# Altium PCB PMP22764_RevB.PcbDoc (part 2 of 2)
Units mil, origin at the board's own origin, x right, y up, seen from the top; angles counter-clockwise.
Board outline 2750 x 1770 mil, 4 copper layers (Top Layer, Signal Layer 1, Signal Layer 2, Bottom Layer), stack 61.2 mil thick; 76 components, 35 nets, 197 pads, 92 vias.
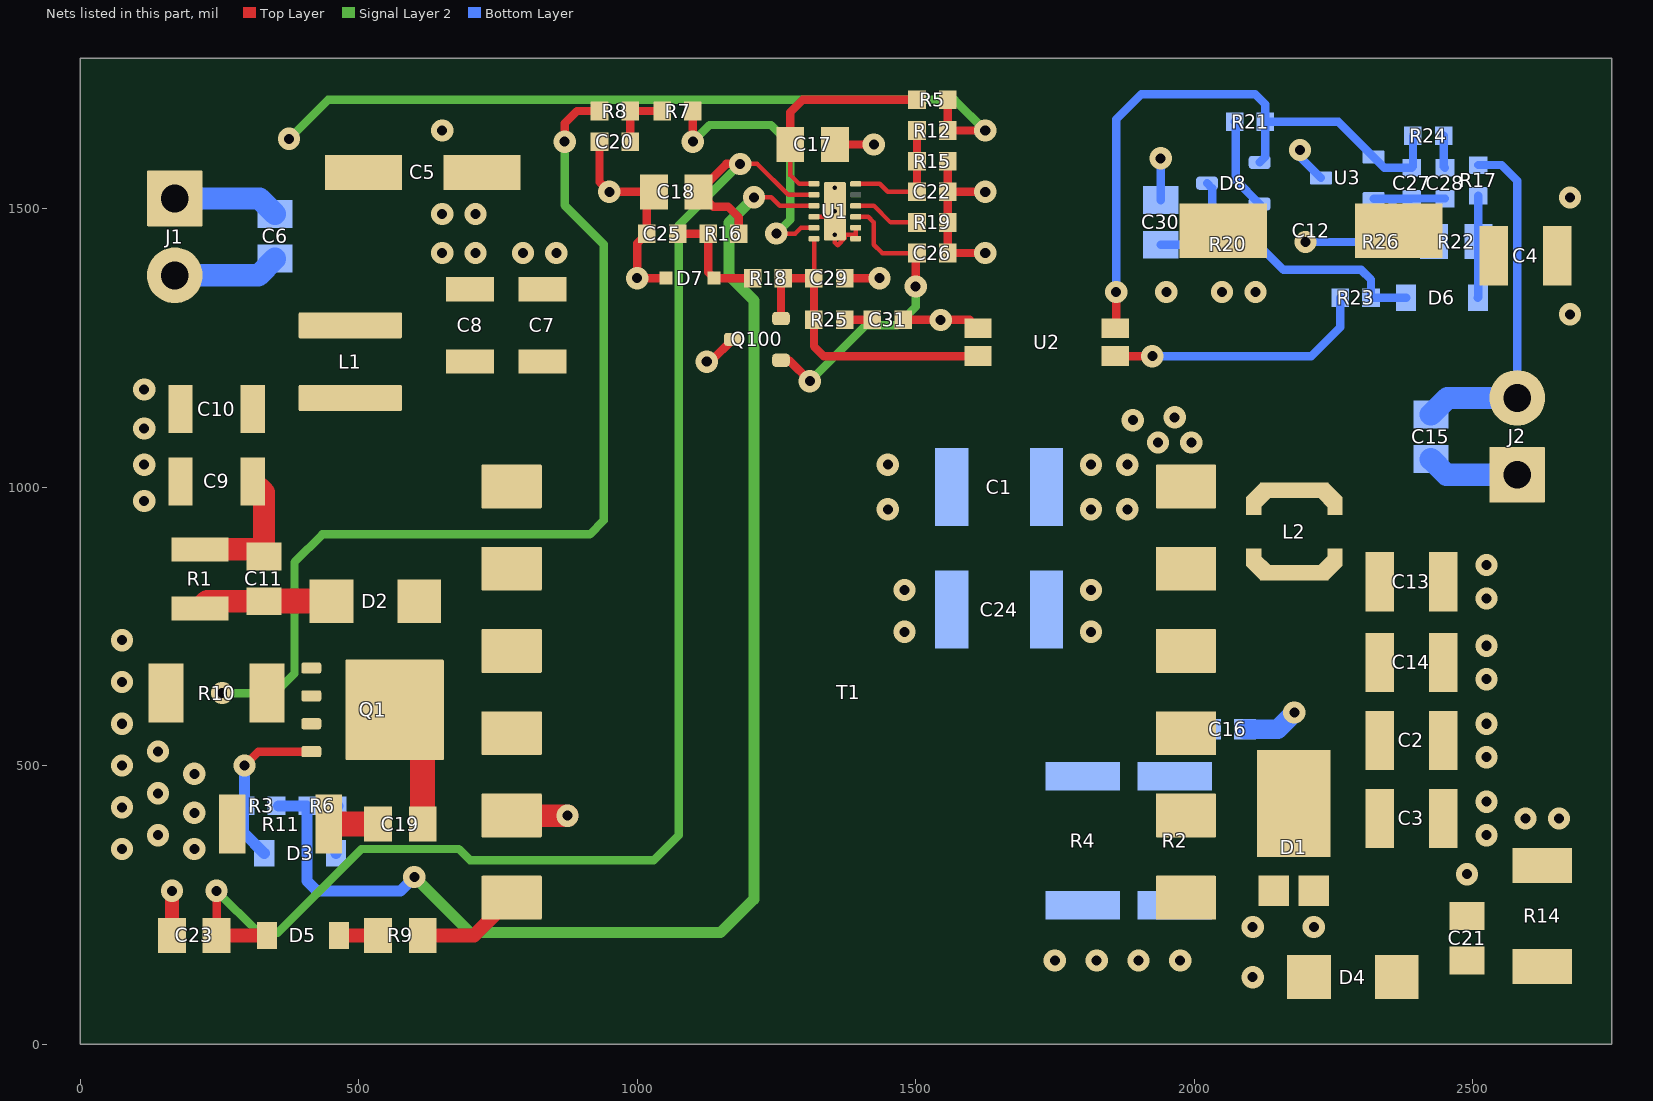
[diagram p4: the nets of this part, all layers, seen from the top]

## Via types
v1: diameter 40, hole 18, Top Layer to Bottom Layer, 89 vias
v2: diameter 19.68, hole 7.87, Top Layer to Bottom Layer, 3 vias

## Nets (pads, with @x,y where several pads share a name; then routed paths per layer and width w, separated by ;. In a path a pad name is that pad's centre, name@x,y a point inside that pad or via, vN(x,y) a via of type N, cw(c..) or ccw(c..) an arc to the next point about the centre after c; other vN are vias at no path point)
D1_K: C2.2 C3.2 C13.1 C14.1 C16.1 D1.3 L2.1 T1.8 T1.9 T1.10 T1.11 | length 100.9
  Bottom Layer w35: C16.1@2091.5,565 2150,565 v1(2180,595)
GND: C1.1 C2.1 C3.1 C4.1 C12.2 C13.2 C14.2 C15.1 C21.2 C24.1 C30.1 J2.1 R14.2 R26.2 T1.12 U3.3 | length 414.7
  Bottom Layer w15: C30.1@1940,1515 v1(1940,1590) ; v1(2190,1605) 2190,1592.76 U3.3@2227.76,1555 ; v1(2200,1440) R26.2@2307.44,1440
  Bottom Layer w40: C15.1@2425,1050 2453,1022 J2.1@2580,1022
  other v1: 2490,305 2525,375 2595,405 2655,405 2525,435 2525,515 2525,575 2525,655 2525,715 1815,740 2525,800 1815,815 2525,860 1815,960 1880,960 1815,1040 1880,1040 1935,1080 1995,1080 1890,1120 1965,1125 2675,1310 1950,1350 2050,1350 2110,1350 2675,1519.87
NetC1_2: C1.2 C7.1 C8.1 C9.1 C10.1 C11.1 L1.2 R1.1 T1.1 T1.2 | length 263.7
  Top Layer w40: R1.1@215,888.15 316.85,888.15 C11.1@330,875 330,989.96 C9.1@309.96,1010
  other v1: 1450,960 1450,1040
NetC4_2: C4.2 C12.1 C15.2 J2.2 L2.2 R17.1 | length 638.6
  Bottom Layer w15: R17.1@2510.39,1578.02 2551.98,1578.02 2580,1550 J2.2@2580,1160
  Bottom Layer w40: C15.2@2425,1130 2455,1160 J2.2@2580,1160
NetC5_1: C5.1 C6.1 J1.1 L1.1 R5.2 R12.1 | length 1615.8
  Top Layer w15: R5.2@1557.56,1695 R12.1@1557.56,1640 v1(1625,1640)
  Signal Layer 2 w15: v1(375,1625) 445,1695 1570,1695 v1(1625,1640)
  Bottom Layer w40: J1.1@170,1518 322,1518 C6.1@350,1490
NetC11_2: C11.2 D2.1 R1.2 | length 241.7
  Top Layer w40: R1.2@215,781.85 228.15,795 C11.2@330,795
  Top Layer w45: C11.2@330,795 D2.1@451.26,795
NetC16_2: C16.2 R2.2 R4.2
NetC17_2: C17.2 R5.1 U1.1 | length 398.7
  Top Layer w8: C17.2@1275,1615 1275,1560 1290.79,1544.21 U1.1@1317.6,1544.21
  Top Layer w15: C17.2@1275,1615 1275,1672.99 1297.01,1695 R5.1@1502.44,1695
NetC18_1: C18.1 C23.2 D5.1 R16.2 U1.2 | length 2743.2
  Top Layer w8: v1(1185,1580.08) 1215.55,1580.08 1271.1,1524.53 U1.2@1317.6,1524.53
  Top Layer w15: C23.2@245,195 v1(245,275) ; R16.2@1182.56,1455 1182.56,1483.9 1163.07,1503.39 1136.61,1503.39 C18.1@1110,1530 1160.08,1580.08 v1(1185,1580.08)
  Top Layer w25: C23.2@245,195 D5.1@335.53,195
  Signal Layer 2 w15: v1(245,275) 320,200 355,200 505,350 680,350 700,330 1030,330 1075,375 1075,1470.08 v1(1185,1580.08)
NetC19_1: C19.1 D2.2 Q1.5 Q1.6 Q1.7 Q1.8 Q1.9@564.61,600 T1.3 T1.4 | length 229.3
  Top Layer w45: Q1.9@564.61,600 565,600.39 610.47,554.92 615,554.92 C19.1@615,395
NetC19_2: C19.2 R11.2 | length 88.4
  Top Layer w45: R11.2@446.61,395 C19.2@535,395
NetC20_2: C20.2 R7.2 R8.1 | length 112.4
  Top Layer w15: C20.2@987.56,1620 R8.1@987.56,1675 R7.2@1045,1675
NetC21_1: C21.1 D4.2 R14.1
NetC22_2: C22.2 R12.2 R15.1 U1.12 | length 225.9
  Top Layer w8: U1.12@1392.4,1544.21 1435.79,1544.21 1450,1530 C22.2@1502.44,1530
  Top Layer w15: C22.2@1502.44,1530 R15.1@1502.44,1585 R12.2@1502.44,1640
NetC25_1: C25.1 D7.1 R16.1 R18.1 | length 208.5
  Top Layer w15: C25.1@1072.56,1455 R16.1@1127.44,1455 1127.44,1385.87 D7.1@1138.31,1375 R18.1@1207.44,1375
NetC26_1: C26.1 Q100.1 U1.9 | length 570.6
  Top Layer w8: U1.9@1392.4,1485.16 1414.84,1485.16 1425,1475 1425,1435 1440,1420 1497.44,1420 C26.1@1502.44,1420
  Top Layer w15: Q100.1@1258.31,1227.6 1272.4,1227.6 v1(1310,1190) ; v1(1500,1360) 1500,1417.56 C26.1@1502.44,1420
  Signal Layer 2 w15: v1(1310,1190) 1410.16,1290.16 1466.73,1290.16 1500,1323.43 v1(1500,1360)
NetC27_1: C27.1 C28.1 R22.2 R26.1 U3.2 | length 276.5
  Bottom Layer w15: U3.2@2322.24,1517.6 2356.17,1517.6 ; R22.2@2430.39,1440.46 2429.94,1440 R26.1@2362.56,1440 2362.56,1484.86 2356.17,1491.25 2356.17,1517.6 ; C28.1@2450.39,1517.9 C27.1@2390.39,1517.9 2390.09,1517.6 2356.17,1517.6
NetC27_2: C27.2 D8.1 R21.2 R24.1 U2.2 U3.1 | length 1133.3
  Top Layer w15: U2.2@1858.03,1285 1860,1286.97 v1(1860,1350)
  Bottom Layer w15: v1(1860,1350) 1860,1660 1905,1705 2110,1705 2127.95,1687.05 R21.2@2127.95,1655.46 ; D8.1@2117.64,1582.86 2127.95,1593.17 R21.2@2127.95,1655.46 ; R24.1@2392.83,1630.46 2392.83,1575.46 C27.2@2390.39,1573.02 2341.63,1573.02 U3.1@2322.24,1592.4 2259.19,1655.46 R21.2@2127.95,1655.46
NetC28_2: C28.2 R24.2 | length 58.5
  Bottom Layer w15: R24.2@2447.95,1630.46 2447.95,1575.46 C28.2@2450.39,1573.02
NetC29_2: C29.2 Q100.2 R18.2 R25.2 U1.6 U2.4 | length 624.3
  Top Layer w8: C29.2@1317.44,1375 1317.6,1375.16 U1.6@1317.6,1445.79
  Top Layer w15: Q100.2@1258.31,1302.4 1258.31,1370.75 R18.2@1262.56,1375 C29.2@1317.44,1375 R25.2@1317.44,1300 1317.44,1252.56 1335,1235 U2.4@1611.97,1235
NetC30_2: C30.2 D8.3 R20.2 | length 206.7
  Bottom Layer w15: C30.2@1940,1435 2032.38,1435 2032.38,1536.23 D8.3@2023.15,1545.46
NetC31_1: C31.1 R25.1 | length 49.9
  Top Layer w15: R25.1@1372.56,1300 C31.1@1422.44,1300
NetD1_1: D1.1 D1.2 D4.1 R2.1 R4.1 T1.7
  other v1: 2105,120 1750,150 1825,150 1900,150 1975,150 2105,210 2215,210
NetD3_1: D3.1 R6.2 | length 86.3
  Bottom Layer w20: D3.1@459.47,342.5 459.47,424.41 R6.2@462.56,427.5
NetD3_2: D3.2 Q1.4 R3.2 | length 303.8
  Top Layer w15: v1(295,500) 320,525 Q1.4@415,525
  Bottom Layer w20: v1(295,500) 295,429 293.5,427.5 293.5,379.53 D3.2@330.53,342.5
NetD5_2: D5.2 R9.2 | length 70.5
  Top Layer w25: D5.2@464.47,195 R9.2@535,195
NetD6_1: D6.1 R17.2 R22.1 | length 183.3
  Bottom Layer w15: D6.1@2509.47,1340 2510.39,1340.93 R22.1@2510.39,1440.46 R17.2@2510.39,1522.9
NetD6_2: D6.2 D8.2 R20.1 R21.1 R23.1 | length 590.8
  Bottom Layer w15: R21.1@2072.83,1655.46 2075,1653.29 2075,1550.69 D8.2@2117.64,1508.06 2117.64,1438.09 2115,1435.46 ; R20.1@2087.95,1435.46 2115,1435.46 ; D6.2@2380.53,1340 R23.1@2317.56,1340 2317.56,1372.44 2300,1390 2160.46,1390 2115,1435.46
NetQ1_1: Q1.1 Q1.2 Q1.3 R8.2 R10.2 | length 1744.1
  Top Layer w15: v1(870,1620) 870,1652.99 892.01,1675 R8.2@932.44,1675
  Signal Layer 2 w15: v1(255,630) 350,630 385,665 385,865 435,915 915,915 940,940 940,1435.83 870,1505.83 v1(870,1620)
NetR3_1: R3.1 R6.1 U1.3 | length 2483.6
  Top Layer w8: v1(1210,1520.08) 1240.92,1520.08 1256.16,1504.84 U1.3@1317.6,1504.84
  Signal Layer 2 w20: v1(600,300) 700,200 1150,200 1210,260 1210,1335 1165,1380 1165,1475.08 v1(1210,1520.08)
  Bottom Layer w20: R3.1@356.5,427.5 R6.1@407.44,427.5 407.44,292.56 425,275 575,275 v1(600,300)
NetR7_1: R7.1 U1.5 | length 499.3
  Top Layer w8: v1(1250,1455.08) 1283.78,1455.08 1294.17,1465.47 U1.5@1317.6,1465.47
  Top Layer w15: v1(1100,1620) 1100,1674.88 R7.1@1100.12,1675
  Signal Layer 2 w15: v1(1100,1620) 1130,1650 1240.31,1650 1275,1615.31 1275,1480.08 v1(1250,1455.08)
NetR9_1: R9.1 T1.6 | length 187.6
  Top Layer w25: R9.1@615,195 707.24,195 T1.6@774.69,262.44
NetR19_1: R19.1 U1.10 | length 122.4
  Top Layer w8: U1.10@1392.4,1504.84 1425.16,1504.84 1455,1475 R19.1@1502.44,1475
NetR23_2: R23.2 U2.1 | length 479
  Top Layer w15: U2.1@1858.03,1235 v1(1925,1235)
  Bottom Layer w15: v1(1925,1235) 2210.47,1235 2262.44,1286.97 R23.2@2262.44,1340
PGND: C5.2 C6.2 C7.2 C8.2 C9.2 C10.2 C17.1 C18.2 C20.1 C22.1 C23.1 C24.2 C25.2 C26.2 C29.1 C31.2 D7.2 J1.2 Q100.3 R10.1 R11.1 R15.2 R19.2 T1.5 U1.4 U1.7 U1.8 U1.13 U2.3 | length 1574.6
  Top Layer w8: U1.4@1317.6,1485.16 1345.16,1485.16 v2(1355,1495) 1355,1438.98 1360,1433.98 1372.99,1446.97 1372.99,1452.85 1389.62,1452.85 1392.4,1455.63 ; U1.7@1392.4,1445.79 1392.4,1455.63 ; U1.8@1392.4,1465.47 1392.4,1455.63
  Top Layer w15: C20.1@932.44,1620 932.44,1547.56 v1(950,1530) C18.2@1030,1530 1017.44,1517.44 C25.2@1017.44,1455 1000,1437.56 v1(1000,1375) D7.2@1051.69,1375 ; v1(1125,1225) 1131.69,1225 Q100.3@1171.69,1265 ; C17.1@1355,1615 v1(1425,1615) ; C29.1@1372.56,1375 v1(1435,1375) ; C31.2@1477.56,1300 v1(1545,1300) 1596.97,1300 U2.3@1611.97,1285 ; R15.2@1557.56,1585 C22.1@1557.56,1530 ; v1(1625,1420) C26.2@1557.56,1420 R19.2@1557.56,1475 C22.1@1557.56,1530 ; v1(1625,1530) C22.1@1557.56,1530
  Top Layer w25: C23.1@165,195 v1(165,275)
  Top Layer w40: T1.5@774.68,410.39 775.08,410 v1(875,410)
  Bottom Layer w40: J1.2@170,1380 320,1380 C6.2@350,1410
  other v1: 75,350 205,350 140,375 205,415 75,425 140,450 205,485 75,500 140,525 75,575 75,650 75,725 1480,740 1480,815 115,975 115,1040 115,1105 115,1175 650,1420 710,1420 795,1420 855,1420 650,1490 710,1490 650,1640
  other v2: 1355,1452.68 1355,1537.32
pads on no net: Q1.9@510.08,542.91 Q1.9@510.08,600 Q1.9@510.08,657.09 Q1.9@546.69,600 Q1.9@580.16,542.91 Q1.9@580.16,600 Q1.9@580.16,657.09 U1.11

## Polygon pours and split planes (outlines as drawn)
PGND on Bottom Layer "BOTTOM_LAYER_PGND_P076" (solid, remove dead copper, pour order 76): 50,50 50,1720 1680,1720 1680,1200 1595,1200 1595,50
GND on Bottom Layer "BOTTOM_LAYER_GND_P066" (solid, remove dead copper, pour order 66): 2700,50 1705,50 1705,1090 1790,1090 1790,1720 2700,1720
NetC16_2 on Bottom Layer "BOTTOM_LAYER_NETC16_2_P062" (solid, remove dead copper, pour order 62): 1725,335 2050,335 2050,600 1725,600
NetD1_1 on Bottom Layer "BOTTOM_LAYER_NETD1_1_P060" (solid, remove dead copper, pour order 60): 2260,305 2260,50 1705,50 1705,305
NetC1_2 on Bottom Layer "BOTTOM_LAYER_NETC1_2_P058" (solid, remove dead copper, pour order 58): 1595,1070 1400,1070 1400,930 1595,930
no net on Bottom Layer "BOTTOM_LAYER_NONET_P000" (solid, remove dead copper, pour order 0): 90,760
no net on Bottom Layer "BOTTOM_LAYER_NONET_P002" (solid, remove dead copper, pour order 2): 106.57,762.09
PGND on Top Layer "TOP_LAYER_PGND_P074" (solid, remove dead copper, pour order 74): 1680,1720 1680,1200 1595,1200 1595,50 50,50 50,1720
GND on Top Layer "TOP_LAYER_GND_P068" (solid, remove dead copper, pour order 68): 2700,50 1705,50 1705,1090 1790,1090 1790,1720 2700,1720
NetC21_1 on Top Layer "TOP_LAYER_NETC21_1_P056" (solid, remove dead copper, pour order 56): 2700,50 2300,50 2300,175 2700,175
NetC4_2 on Top Layer "TOP_LAYER_NETC4_2_P054" (solid, remove dead copper, pour order 54): 2085,945 2085,1250 2250,1250 2250,1700 2580,1700 2580,1250 2700,1250 2700,1105 2450,1105 2450,945
D1_K on Top Layer "TOP_LAYER_D1_K_P052" (solid, remove dead copper, pour order 52): 2375,335 1705,335 1705,600 1900,600 1900,895 2375,895
NetD1_1 on Top Layer "TOP_LAYER_NETD1_1_P050" (solid, remove dead copper, pour order 50): 2260,305 1705,305 1705,50 2260,50
NetQ1_1 on Top Layer "TOP_LAYER_NETQ1_1_P048" (solid, remove dead copper, pour order 48): 435,700 435,565 235,565 235,700
NetC19_1 on Top Layer "TOP_LAYER_NETC19_1_P046" (solid, remove dead copper, pour order 46): 830,765 680,765 680,865 550,865 550,700 475,700 475,500 830,500
NetC1_2 on Top Layer "TOP_LAYER_NETC1_2_P044" (solid, remove dead copper, pour order 44): 900,930 1500,930 1500,1070 900,1070 900,1270 635,1270 635,1185 270,1185 270,950 715,950 715,800 900,800
NetC5_1 on Top Layer "TOP_LAYER_NETC5_1_P043" (solid, remove dead copper, pour order 43): 50,1465 300,1465 300,1265 600,1265 600,1720 50,1720
GND on Signal Layer 1 "SIGNAL_LAYER_1_GND_P064" (solid, remove dead copper, pour order 64): 1705,50 2700,50 2700,1720 1790,1720 1790,1090 1705,1090
PGND on Signal Layer 1 "SIGNAL_LAYER_1_PGND_P072" (solid, remove dead copper, pour order 72): 1595,50 50,50 50,1720 1680,1720 1680,1200 1595,1200
GND on Signal Layer 2 "SIGNAL_LAYER_2_GND_P070" (solid, remove dead copper, pour order 70): 1705,50 1705,1090 1790,1090 1790,1720 2700,1720 2700,50
PGND on Signal Layer 2 "SIGNAL_LAYER_2_PGND_P078" (solid, remove dead copper, pour order 78): 50,1720 50,50 1595,50 1595,1200 1680,1200 1680,1720

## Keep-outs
Keep-Out Layer:
  text ".Layer_Name" at 577,-858.49 h60

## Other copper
Top Layer:
  text ".Layer_Name" at 577,-858.49 h60
Bottom Layer:
  text ".Layer_Name" at 577,-858.49 h60

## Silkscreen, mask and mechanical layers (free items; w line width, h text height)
Top Overlay:
  text "VIN" at 130,1610 h50
  text "VOUT" at 2500,1267.09 h50
  text "RTN" at 120,1240 h50
  text "GND" at 2595,888.15 h50
  text ".Layer_Name" at 577,-858.49 h60
Bottom Overlay:
  text "'.PRJ_Number'.PCB_Rev" at 1339.25,750 h108.27
  text ".Layer_Name" at 577,-858.49 h60
Top Paste:
  text ".Layer_Name" at 577,-858.49 h60
Bottom Paste:
  text ".Layer_Name" at 577,-858.49 h60
Top Solder:
  text ".Layer_Name" at 577,-858.49 h60
  text ".Layer_Name" at 577,-858.49 h60
Bottom Solder:
  text ".Layer_Name" at 577,-858.49 h60
Drill Guide:
  text ".Layer_Name" at 577,-858.49 h60
M1 Board Outline:
  the board outline again, w10
  text ".Layer_Name" at 577,-858.49 h60
M2 Board Dimensions:
  rectangle: 0,-275 125,-150
  rectangle: 125,-400 500,-275
  lines w7: 0,-275 1000,-275 ; 125,-400 125,-150 ; 250,-400 250,-150 ; 500,-400 500,-150 ; 750,-400 750,-150 ; 0,-400 1000,-400 1000,-150 0,-150 0,-400
  text ".Layer_Name" at 577,-858.49 h60
M3 3D STEP Top:
  text ".Layer_Name" at 577,-858.49 h60
M4 3D STEP Bottom:
  text ".Layer_Name" at 577,-858.49 h60
M5 Assembly Top:
  lines w10: -292,-930.17 6308,-930.17 ; -292,-726.83 6310,-726.83 ; -292,-523.5 -292,-1133.5 3713,-1133.5 6310,-1133.5 6310,-523.5 -291.5,-523.5 -291.5,-1133.5 1284,-1133.5 ; 2173,-1133.5 2173,-523.5 ; 3440,-726.83 3440,-523.5 ; 4280,-726.83 4280,-523.5 ; 4902,-1140 4902,-937.17
  text "COMPONENTS MARKED 'DNP' SHOULD NOT BE POPULATED." at 1153.5,-318.5 h60
  text "ASSEMBLY VARIANT:" at 1153,-434 h60
  text ".VariantName" at 2189,-434 h60
  text "PCB VIEWED FROM TOP SIDE" at -228.5,-655.67 h60
  text "BOARD #:" at 2248,-655.67 h60
  text ".PRJ_Number" at 2793.5,-655.67 h60
  text "REV:" at 3638,-655.67 h60
  text ".PCB_Rev" at 3929.5,-655.67 h60
  text "SVN REV:" at 4476,-655.67 h60
  text ".VersionControl_RevNumber" at 4982,-655.67 h60
  text "TID #:" at 2248,-859 h60
  text ".TID" at 2793.5,-859 h60
  text "PLOT NAME =" at -228.5,-1064.34 h60
  text ".plot_File_Name" at 577,-1064.34 h60
  text "GENERATED    :" at 2250,-1064.34 h60
  text ".Print_Date" at 3119.5,-1064.34 h60
  text ".Print_Time" at 3848.5,-1064.34 h60
  text "TEXAS INSTRUMENTS" at 5113,-1064.34 h60
M6 Assembly Bottom:
  lines w10: -292.5,-727.33 6309.5,-727.33 ; -290.5,-930.67 6309.5,-930.67 ; 1115.5,-1140.5 1115.5,-937.67 ; 1737.5,-727.33 1737.5,-524 ; 2577.5,-727.33 2577.5,-524 ; 3844.5,-1134 3844.5,-524 ; 4733.5,-1134 6309,-1134 6309,-524 -292.5,-524 -292.5,-1134 2304.5,-1134 6309.5,-1134 6309.5,-524
  text "COMPONENTS MARKED 'DNP' SHOULD NOT BE POPULATED." at 6102,-318 h60
  text ".VariantName" at 5058,-434 h60
  text "ASSEMBLY VARIANT:" at 6097,-434 h60
  text ".VersionControl_RevNumber" at 1035.5,-656.17 h60
  text "SVN REV:" at 1541.5,-656.17 h60
  text ".PCB_Rev" at 2088,-656.17 h60
  text "REV:" at 2379.5,-656.17 h60
  text ".PRJ_Number" at 3224,-656.17 h60
  text "BOARD #:" at 3769.5,-656.17 h60
  text "PCB VIEWED FROM BOTTOM SIDE" at 6246,-656.17 h60
  text ".TID" at 3224,-859.5 h60
  text "TID #:" at 3769.5,-859.5 h60
  text "TEXAS INSTRUMENTS" at 904.5,-1064.84 h60
  text ".Print_Time" at 2169,-1064.84 h60
  text ".Print_Date" at 2898,-1064.84 h60
  text "GENERATED    :" at 3767.5,-1064.84 h60
  text ".plot_File_Name" at 5440.5,-1064.84 h60
  text "PLOT NAME =" at 6246,-1064.84 h60
M9 Title Sheet:
  drawing of 57 lines, arcs and shapes, not listed
  text "1" at 739.84,8036.5 h70
  text "2" at 3235.5,8036.5 h70
  text "3" at 5724.84,8036.5 h70
  text "4" at 8231.51,8036.5 h70
  text "5" at 10730.5,8036.5 h70
  text "6" at 13235.5,8036.5 h70
  text "A" at -416.5,6893.5 h70
  text "A" at 14383.5,6893.5 h70
  text "B" at -416.5,4513.5 h70
  text "B" at 14383.5,4513.5 h70
  text "C" at -416.5,2138.5 h70
  text "C" at 14383.5,2138.5 h70
  text "PROJECT TITLE:" at 11343.5,277.5 h45
  text ".PRJ_Title" at 11393.5,144.17 h70
  text "DESIGNED FOR:" at 11343.5,-23.5 h45
  text ".PRJ_Customer" at 11393.5,-163.5 h70
  text "D" at -416.5,-231.5 h70
  text "D" at 14383.5,-231.5 h70
  text "FILE NAME:" at 11343.5,-323.5 h45
  text ".PCB_File_Name_No_Path" at 11393.5,-443.5 h70
  text "Texas Instruments (TI) and/or its licensors do not warrant the accuracy or completeness of this specification" at 6374,-605.34 h45
  text "ENGINEER:" at 11343.5,-613.5 h45
  text "LAYOUT BY:" at 12848.5,-613.5 h45
  text "or any information contained therein. TI and/or its licensors do not warrant that this design will meet" at 6329.01,-718 h45
  text ".PRJ_Engineer" at 11393.5,-768.49 h70
  text ".PCB_Layout" at 12899,-768.49 h70
  text "the specifications, will be suitable for your application or fit for any particular purpose, or will operate in" at 6329.01,-830.67 h45
  text ".Layer_Name" at 577,-858.49 h60
  text "ALTIUM DESIGNER VERSION:" at 12848.5,-923.5 h45
  text "an implementation. TI and/or its licensors do not warrant that the design is production worthy. You should" at 6329.01,-943.33 h45
  text "completely validate and test your design implementation to confirm the system functionality for your application." at 6374,-1056 h45
  text ".print_Scale" at 11393.5,-1056.83 h70
  text ".Application_BuildNumber" at 12899,-1056.83 h70
  text "1" at 739.84,-1263.5 h70
  text "2" at 3235.5,-1263.5 h70
  text "3" at 5724.84,-1263.5 h70
  text "4" at 8231.51,-1263.5 h70
  text "5" at 10730.5,-1263.5 h70
  text "6" at 13235.5,-1263.5 h70
M10 Fab Notes:
  drawing of 189 lines, arcs and shapes, not listed
  text "DESIGN INFORMATION" at 12382.02,6356.17 h60
  text "MIN. TRACK WIDTH:" at 11737.46,6224.05 h60
  text "8" at 12833.7,6224.05 h60
  text "MIL" at 12988.46,6224.05 h60
  text "MIN. CLEARANCE:" at 11737.46,6099.92 h60
  text "0.2" at 12773.7,6099.93 h60
  text "mm" at 12988.46,6099.92 h60
  text "MIN. VIA PAD SIZE:" at 11737.46,5975.8 h60
  text "24" at 12803.71,5975.8 h60
  text "MIL" at 12988.46,5975.8 h60
  text "0.05mm (2MIL)" at 12432.46,5845.9 h60
  text "MINIMUM ANNULAR RING" at 11408.23,5837.67 h60
  text "EXTERNAL" at 13140.46,5837.67 h60
  text "PER" at 11608.23,5727.55 h60
  text "IPC-D-275 CLASS 2 LEVEL C" at 11828.23,5727.54 h60
  text "MIL, HOLES" at 13316.46,5627.07 h60
  text "+/-" at 12924,5618.48 h60
  text "+/-" at 13778,5618.48 h60
  text "REGISTRATION TOLERANCES:" at 11408.23,5617.42 h60
  text "METAL" at 12608,5617.42 h60
  text "5" at 13184.2,5617.42 h60
  text "3" at 14017.2,5617.42 h60
  text "MIL" at 14133.46,5617.42 h60
  text "HOLE SIZE TOLERANCE (UNLESS OTHERWISE SPECIFIED):" at 11408.23,5519.1 h60
  text "+/-" at 13778,5516.23 h60
  text "3" at 14017.2,5515.17 h60
  text "MIL" at 14133.46,5515.17 h60
  text "MATERIAL:" at 11333.46,5377.52 h60
  text "FR-4 High Tg" at 12319.9,5249 h60
  text "X" at 12175.46,5241.01 h60
  text "FR-408" at 11754.46,5236.49 h60
  text "OTHER" at 13242.46,5236.49 h60
  text "62 MIL (1.6mm) +/-10%" at 12074.56,5093.46 h60
  text "X" at 11954.46,5091.01 h60
  text "THICKNESS:" at 11408.23,5085.24 h60
  text "OTHER" at 13359.46,5085.24 h60
  text "TOLERANCE:" at 11408.23,4946.92 h60
  text "X" at 12256.46,4946.92 h60
  text "ANSI IPC-6012 TYPE 3 CLASS 2" at 12434.48,4946.92 h60
  text "OTHER +/-" at 12434.46,4802.73 h60
  text "BOW & TWIST:" at 11408.23,4657.54 h60
  text "X" at 12256.46,4657.54 h60
  text "ANSI IPC-6012 TYPE 3 CLASS 2" at 12434.48,4657.54 h60
  text "OTHER +/-" at 12434.46,4510.85 h60
  text "DRILLING:" at 11333.46,4380.23 h60
  text "NC_DRILL FILES" at 13094.46,4275.04 h60
  text "REFERENCE:" at 11408.23,4271.1 h60
  text "X" at 12065.46,4271.01 h60
  text "AS SHOWN" at 12243.46,4271.1 h60
  text "X" at 12966.46,4271.1 h60
  text "OTHER" at 13392.46,4128.85 h60
  text "PTH COPPER THICKNESS:" at 11407.91,4125.32 h60
  text "X" at 12547.14,4125.32 h60
  text "20-30 um" at 12675.14,4125.32 h60
  text "BOARD FINISH:" at 11333.46,3977.73 h60
  text "SILKSCREEN:" at 11488.68,3867.6 h60
  text "X" at 12446.46,3867.6 h60
  text "TOP" at 12563.46,3867.6 h60
  text "X" at 12956.46,3867.6 h60
  text "BOTTOM" at 13074.46,3867.6 h60
  text "SILKSCREEN COLOR:" at 11488.68,3712.41 h60
  text "X" at 12445.46,3712.41 h60
  text "WHITE" at 12563.46,3712.41 h60
  text "OTHER" at 13074.46,3712.41 h60
  text "X" at 12576.46,3568.96 h60
  text "GREEN" at 12694.46,3568.96 h60
  text "OTHER" at 13312.46,3568.96 h60
  text "SOLDER RESIST COLOR:" at 11488.68,3562.1 h60
  text "X" at 12576.46,3414.71 h60
  text "MATTE" at 12694.46,3414.71 h60
  text "SEMI-GLOSS" at 13312,3414.07 h60
  text "IMMERSION GOLD (ENIG)" at 12394.46,3241.94 h60
  text "ENEPIG" at 13732,3234.72 h60
  text "SURFACE FINISH:" at 11333.46,3233.72 h60
  text "X" at 12216.46,3233.72 h60
  text "IMM. TIN/SILVER OR EQUIV" at 11663,3096.4 h60
  text "OTHER" at 13094.46,3092.47 h60
  text "ARRAY/PANEL:" at 11333.46,2937.09 h60
  text "X" at 12210,2935 h60
  text "CUT AND TRIM PER M1 BOARD OUTLINE" at 12394.46,2928.87 h60
  text "N.C. ROUTE" at 12394.46,2792.9 h60
  text "V. SCORE" at 13260.46,2792.9 h60
  text "CERTIFICATION:" at 11333.46,2663.77 h60
  text "MATERIALS AND WORKMANSHIP FOR ALL PCBS" at 12058.46,2663.77 h60
  text "TO MEET OR EXCEED THE REQUIREMENTS OF:" at 12058.46,2569.71 h60
  text "X" at 11695.97,2441.08 h60
  text "ANSI IPC-A-600F CLASS ->" at 11823.96,2441.08 h60
  text "X" at 13471.97,2441.08 h60
  text "2" at 13581.96,2441.08 h60
  text "1" at 13266.96,2439.58 h60
  text "3" at 13935.96,2439.58 h60
  text "X" at 12507.97,2293.39 h60
  text "RoHS" at 12635.96,2293.39 h60
  text "OTHER" at 13280.36,2293.39 h60
  text "PER ORDER" at 13677.42,2293.39 h60
  text "ALL BOARDS MUST MEET OR EXCEED UL94-V0 REQUIREMENTS." at 11361,2139.57 h60
  text "PCB MUST BEAR THE UL94V-0 UL REGISTERED MATERIAL ID NUMBER" at 11361,2023.5 h60
  text "ADDITIONAL REQUIREMENTS:" at 11333.46,1854.08 h60
  text "MICROSECTION:" at 11408.23,1746.95 h60
  text "YES" at 12313.96,1746.95 h60
  text "REQUIRED" at 13175.46,1602.62 h60
  text "BARE BOARD ELEC. TEST:" at 11408.23,1599.76 h60
  text "NONE" at 12713.96,1599.76 h60
  text "X" at 13057.46,1599.76 h60
  text "PER ORDER" at 13767.46,1599.76 h60
  text "XX MIL VIAS REQUIRE NON-CONDUCTIVE FILL AND PLANARIZE" at 11576.38,1394.82 h59
  text "XX MIL VIAS REQUIRE CONDUCTIVE FILL AND PLANARIZE" at 11584.38,1290.84 h60
  text "OUTER XX MIL TRACES REQUIRE 50 OHM SINGLE-ENDED IMPEDANCE" at 11583.39,1127.46 h58
  text "LAYER 2 & 3 (INNER LAYERS) XX MIL WIDE, XX MIL SPACE / TRACES REQUIRE 100 OHM DIFFERENTIAL IMPEDANCE" at 11575.39,891.74 h60
  text ".Layer_Name" at 577,-858.49 h60
M11 Gerber Information:
  lines w10: -292,-930.17 6308,-930.17 ; -292,-726.83 6310,-726.83 ; -292,-523.5 -292,-1133.5 3713,-1133.5 6310,-1133.5 6310,-523.5 -291.5,-523.5 -291.5,-1133.5 1284,-1133.5 ; 2173,-1133.5 2173,-523.5 ; 3440,-726.83 3440,-523.5 ; 4280,-726.83 4280,-523.5 ; 4902,-1140 4902,-937.17
  text "ALL ARTWORK VIEWED FROM TOP SIDE" at -228.5,-655.67 h60
  text "BOARD #:" at 2248,-655.67 h60
  text ".PRJ_Number" at 2793.5,-655.67 h60
  text "REV:" at 3638,-655.67 h60
  text ".PCB_Rev" at 3929.5,-655.67 h60
  text "SVN REV:" at 4476,-655.67 h60
  text ".VersionControl_RevNumber" at 4982,-655.67 h60
  text "LAYER NAME =" at -228.5,-858.49 h60
  text "TID #:" at 2248,-859 h60
  text ".TID" at 2793.5,-859 h60
  text "PLOT NAME =" at -228.5,-1064.34 h60
  text ".plot_File_Name" at 577,-1064.34 h60
  text "GENERATED    :" at 2250,-1064.34 h60
  text ".Print_Date" at 3119.5,-1064.34 h60
  text ".Print_Time" at 3848.5,-1064.34 h60
  text "TEXAS INSTRUMENTS" at 5113,-1064.34 h60
M12 Stackup:
  drawing of 295 lines, arcs and shapes, not listed
  text "Layer" at 9770.88,7839.68 h60
  text "Name" at 10180.8,7839.68 h60
  text "Material" at 11120.54,7839.68 h60
  text "Thickness" at 11980.3,7839.68 h60
  text "Constant" at 12630.14,7839.68 h60
  text "Board Layer Stack" at 13200,7839.68 h60
  text "1" at 9770.88,7719.68 h60
  text "Top Overlay" at 10180.8,7719.68 h60
  text "2" at 9770.88,7599.68 h60
  text "Top Solder" at 10180.8,7599.68 h60
  text "Solder Resist" at 11120.54,7599.68 h60
  text "0.40mil" at 11980.3,7599.68 h60
  text "3.5" at 12630.14,7599.68 h60
  text "3" at 9770.88,7479.68 h60
  text "Top Layer" at 10180.8,7479.68 h60
  text "Copper" at 11120.54,7479.68 h60
  text "2.80mil" at 11980.3,7479.68 h60
  text "4" at 9770.88,7359.68 h60
  text "Dielectric1" at 10180.8,7359.68 h60
  text "FR-4" at 11120.54,7359.68 h60
  text "15.00mil" at 11980.3,7359.68 h60
  text "4.8" at 12630.14,7359.68 h60
  text "5" at 9770.88,7239.68 h60
  text "Signal Layer 1" at 10180.8,7239.68 h60
  text "Copper" at 11120.54,7239.68 h60
  text "2.80mil" at 11980.3,7239.68 h60
  text "6" at 9770.88,7119.68 h60
  text "Dielectric 2" at 10180.8,7119.68 h60
  text "20.00mil" at 11980.3,7119.68 h60
  text "4.2" at 12630.14,7119.68 h60
  text "7" at 9770.88,6999.68 h60
  text "Signal Layer 2" at 10180.8,6999.68 h60
  text "Copper" at 11120.54,6999.68 h60
  text "2.80mil" at 11980.3,6999.68 h60
  text "8" at 9770.88,6879.68 h60
  text "Dielectric 3" at 10180.8,6879.68 h60
  text "FR-4" at 11120.54,6879.68 h60
  text "15.00mil" at 11980.3,6879.68 h60
  text "4.2" at 12630.14,6879.68 h60
  text "9" at 9770.88,6759.68 h60
  text "Bottom Layer" at 10180.8,6759.68 h60
  text "Copper" at 11120.54,6759.68 h60
  text "2.80mil" at 11980.3,6759.68 h60
  text "10" at 9770.88,6639.68 h60
  text "Bottom Solder" at 10180.8,6639.68 h60
  text "Solder Resist" at 11120.54,6639.68 h60
  text "0.40mil" at 11980.3,6639.68 h60
  text "3.5" at 12630.14,6639.68 h60
  text "11" at 9770.88,6519.68 h60
  text "Bottom Overlay" at 10180.8,6519.68 h60
  text ".Layer_Name" at 577,-858.49 h60
M13 Component Bodies Top:
  text ".Layer_Name" at 577,-858.49 h60
M14 Component Bodies Bottom:
  text ".Layer_Name" at 577,-858.49 h60
M15 Courtyards Top:
  text ".Layer_Name" at 577,-858.49 h60
M16 Courtyards Bottom:
  text ".Layer_Name" at 577,-858.49 h60
Drill Drawing:
  lines w10: 3170.98,242.1 3226.1,242.1 3226.1,297.22 3170.98,297.22 3170.98,242.1 ; 3170.98,379.91 3184.76,379.91 3198.54,366.13 3212.32,379.91 3226.1,379.91 3212.32,393.69 3226.1,407.47 3212.32,407.47 3198.54,421.25 3184.76,407.47 3170.98,407.47 3184.76,393.69 3170.98,379.91 ; 3170.98,545.28 3226.1,545.28 3198.54,490.15 3170.98,545.28
  lines w12: 3121,204.89 6347.8,204.89 ; 3121,576.97 6347.8,576.97 ; 3458.36,80.87 3458.36,701 ; 3790.06,80.87 3790.06,701 ; 4425.91,80.87 4425.91,701 ; 4684.71,80.87 4684.71,701 ; 5059.46,80.87 5059.46,701 ; 5782,80.87 5782,701 ; 3121,80.87 6347.8,80.87 6347.8,701 3121,701 3121,80.87
  text "Symbol" at 3195.42,614.18 h72
  text "Quantity" at 3495.57,614.18 h72
  text "Finished Hole Size" at 3827.26,614.18 h72
  text "Plated" at 4463.12,614.18 h72
  text "Hole Type" at 4721.92,614.18 h72
  text "Drill Layer Pair" at 5096.67,614.18 h72
  text "Hole Tolerance" at 5819.21,614.18 h72
  text "3" at 3495.57,490.15 h60
  text "7.87mil (0.200mm)" at 3827.26,490.15 h60
  text "PTH" at 4463.12,490.15 h60
  text "Round" at 4721.92,490.15 h60
  text "Top Layer - Bottom Layer" at 5096.67,490.15 h60
  text "89" at 3495.57,366.13 h60
  text "18.00mil (0.457mm)" at 3827.26,366.13 h60
  text "PTH" at 4463.12,366.13 h60
  text "Round" at 4721.92,366.13 h60
  text "Top Layer - Bottom Layer" at 5096.67,366.13 h60
  text "4" at 3495.57,242.1 h60
  text "50.00mil (1.270mm)" at 3827.26,242.1 h60
  text "PTH" at 4463.12,242.1 h60
  text "Round" at 4721.92,242.1 h60
  text "Top Layer - Bottom Layer" at 5096.67,242.1 h60
  text "96 Total" at 3495.57,118.07 h60
  text ".Layer_Name" at 577,-858.49 h60
M17 Embedded Cavity:
  text ".Layer_Name" at 577,-858.49 h60
M18 Embedded Assembly:
  text ".Layer_Name" at 577,-858.49 h60
M19 Embedded Keepout:
  text ".Layer_Name" at 577,-858.49 h60

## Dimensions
0,-400 to 1000,-400 on M2 Board Dimensions
0,0 to 0,1770 on M2 Board Dimensions
0,0 to 2750,0 on M2 Board Dimensions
